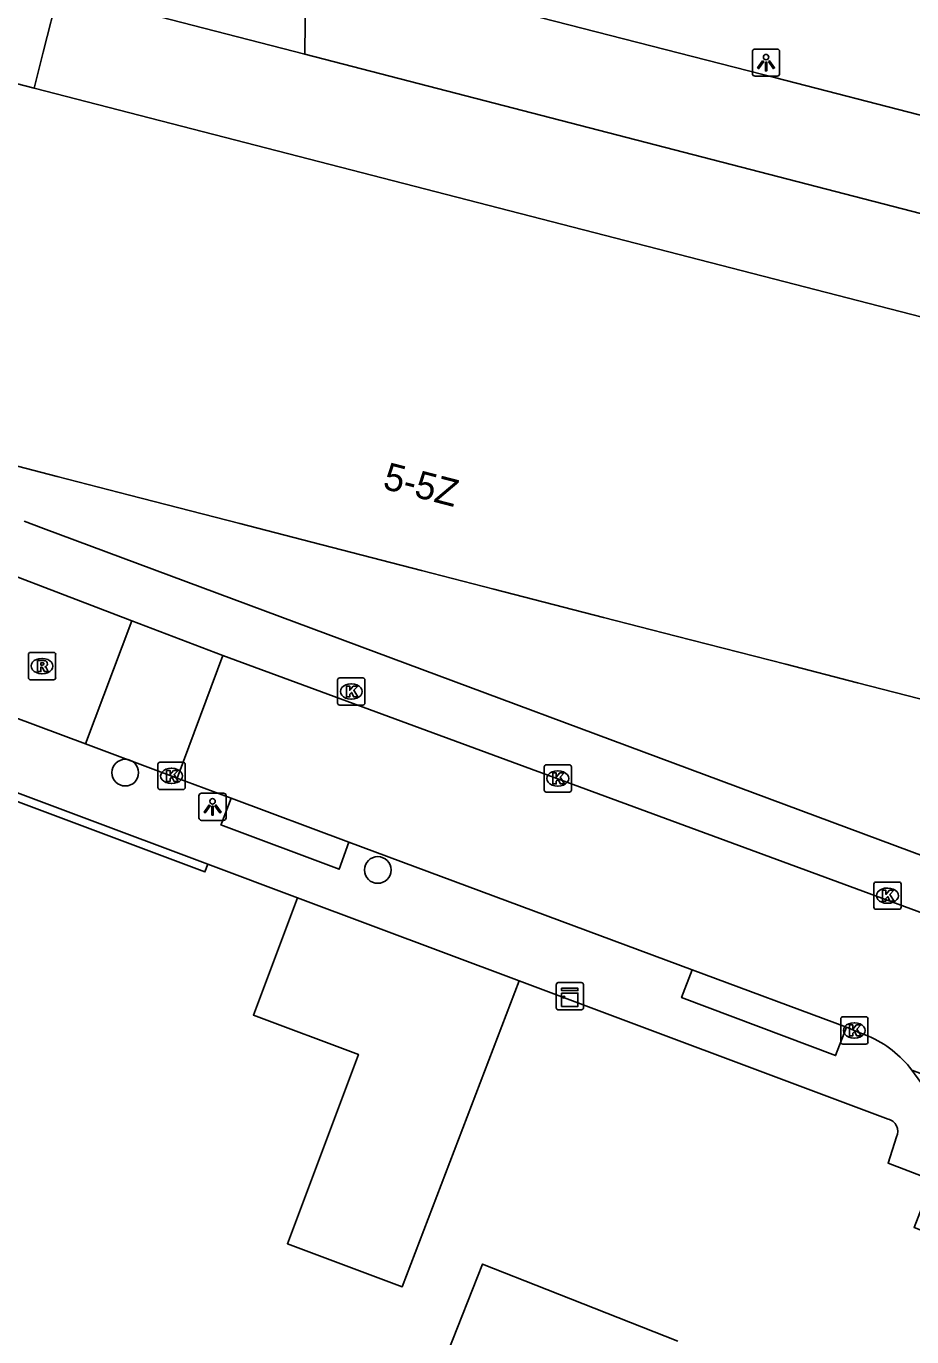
# Model space of a CAD drawing. Extents: x 160664 to 161506, y 382245 to 383288.
# Drawn here: x 161194.13 to 161226.63, y 382834.13 to 382882.22 of the extents above; entities that cross this region are included whole.
import ezdxf

# ---------------------------------------------------------------- set-up
doc = ezdxf.new("R2010")
doc.units = 0
for name, color, linetype in [('IMGEO_Boom', 7, 'Continuous'), ('IMGEO_Kast', 7, 'Continuous'), ('IMGEO_Kolk', 7, 'Continuous'), ('IMGEO_Lichtpunt', 7, 'Continuous'), ('IMGEO_Muur', 7, 'Continuous'), ('IMGEO_Pand', 7, 'Continuous'), ('IMGEO_Pand_nummerreeks', 7, 'Continuous'), ('IMGEO_Rijbaan_lokaal_open', 7, 'Continuous'), ('IMGEO_Rioolput', 7, 'Continuous'), ('IMGEO_Voetpad_open', 7, 'Continuous')]:
    doc.layers.add(name, color=color, linetype=linetype)

msp = doc.modelspace()

# ---------------------------------------------------------------- linework, layer by layer
at = {"layer": 'IMGEO_Boom'}
for centre in [(161197.768, 382854.83), (161207.033, 382851.258)]:
    msp.add_circle(centre, 0.489, dxfattribs=at)
at = {"layer": 'IMGEO_Kast'}
for p, q in [((161213.582, 382846.202), (161213.582, 382847.043)), ((161213.582, 382847.043), (161213.582, 382846.202)), ((161213.657, 382847.127), (161214.498, 382847.127)), ((161214.498, 382847.127), (161213.657, 382847.127)), ((161214.582, 382847.052), (161214.582, 382846.211)), ((161214.582, 382846.211), (161214.582, 382847.052)), ((161214.507, 382846.127), (161213.666, 382846.127)), ((161213.666, 382846.127), (161214.507, 382846.127))]:
    msp.add_line(p, q, dxfattribs=at)
for points in [[(161213.777, 382846.917), (161214.377, 382846.917), (161214.377, 382846.832), (161213.777, 382846.832), (161213.777, 382846.917)], [(161213.777, 382846.742), (161214.377, 382846.742), (161214.377, 382846.253), (161213.777, 382846.253), (161213.777, 382846.742)]]:
    msp.add_lwpolyline(points, dxfattribs=at)
msp.add_circle((161213.861, 382846.591), 0.0377, dxfattribs=at)
for centre, start, end in [((161213.66, 382847.049), 92.4484, 184.2845), ((161213.66, 382847.049), 92.4484, 184.2845), ((161214.504, 382847.049), 2.4484, 94.2845), ((161214.504, 382847.049), 2.4484, 94.2845), ((161213.66, 382846.205), 182.4484, 274.2845), ((161213.66, 382846.205), 182.4484, 274.2845), ((161214.504, 382846.205), 272.4484, 4.2845), ((161214.504, 382846.205), 272.4484, 4.2845)]:
    msp.add_arc(centre, 0.0779, start, end, dxfattribs=at)
at = {"layer": 'IMGEO_Kolk'}
for p, q in [((161205.561, 382857.382), (161205.561, 382858.234)), ((161205.636, 382858.308), (161206.488, 382858.308)), ((161206.049, 382858.088), (161206.074, 382858.088)), ((161206.562, 382858.234), (161206.562, 382857.382)), ((161206.072, 382857.528), (161206.047, 382857.528)), ((161206.488, 382857.308), (161205.636, 382857.308)), ((161198.966, 382854.284), (161198.966, 382855.136)), ((161199.041, 382855.21), (161199.893, 382855.21)), ((161199.967, 382855.136), (161199.967, 382854.284)), ((161213.215, 382855.118), (161214.067, 382855.118)), ((161199.454, 382854.99), (161199.479, 382854.99)), ((161213.14, 382854.192), (161213.14, 382855.044)), ((161213.628, 382854.898), (161213.653, 382854.898)), ((161214.141, 382855.044), (161214.141, 382854.192)), ((161199.893, 382854.21), (161199.041, 382854.21)), ((161199.477, 382854.43), (161199.452, 382854.43)), ((161214.067, 382854.118), (161213.215, 382854.118)), ((161213.651, 382854.338), (161213.626, 382854.338)), ((161225.236, 382849.889), (161225.236, 382850.741)), ((161225.311, 382850.815), (161226.163, 382850.815)), ((161226.237, 382850.741), (161226.237, 382849.889)), ((161225.724, 382850.595), (161225.749, 382850.595)), ((161226.163, 382849.815), (161225.311, 382849.815)), ((161225.747, 382850.035), (161225.722, 382850.035)), ((161224.021, 382844.944), (161224.021, 382845.796)), ((161224.096, 382845.87), (161224.948, 382845.87)), ((161224.509, 382845.65), (161224.534, 382845.65)), ((161225.022, 382845.796), (161225.022, 382844.944)), ((161224.532, 382845.09), (161224.507, 382845.09)), ((161224.948, 382844.87), (161224.096, 382844.87))]:
    msp.add_line(p, q, dxfattribs=at)
for points in [[(161205.561, 382857.382), (161205.561, 382858.234)], [(161205.636, 382858.308), (161206.488, 382858.308)], [(161205.882, 382858.008), (161206.005, 382858.008), (161206.005, 382857.857), (161206.135, 382858.008), (161206.299, 382858.008), (161206.153, 382857.857), (161206.306, 382857.608), (161206.154, 382857.608), (161206.069, 382857.772), (161206.005, 382857.705), (161206.005, 382857.608), (161205.882, 382857.608), (161205.882, 382858.008)], [(161206.562, 382858.234), (161206.562, 382857.382)], [(161206.488, 382857.308), (161205.636, 382857.308)], [(161198.966, 382854.284), (161198.966, 382855.136)], [(161199.041, 382855.21), (161199.893, 382855.21)], [(161199.967, 382855.136), (161199.967, 382854.284)], [(161213.215, 382855.118), (161214.067, 382855.118)], [(161199.287, 382854.91), (161199.41, 382854.91), (161199.41, 382854.759), (161199.54, 382854.91), (161199.704, 382854.91), (161199.558, 382854.759), (161199.711, 382854.51), (161199.559, 382854.51), (161199.474, 382854.674), (161199.41, 382854.607), (161199.41, 382854.51), (161199.287, 382854.51), (161199.287, 382854.91)], [(161213.14, 382854.192), (161213.14, 382855.044)], [(161213.461, 382854.818), (161213.584, 382854.818), (161213.584, 382854.667), (161213.714, 382854.818), (161213.878, 382854.818), (161213.732, 382854.667), (161213.885, 382854.418), (161213.733, 382854.418), (161213.648, 382854.582), (161213.584, 382854.515), (161213.584, 382854.418), (161213.461, 382854.418), (161213.461, 382854.818)], [(161214.141, 382855.044), (161214.141, 382854.192)], [(161199.893, 382854.21), (161199.041, 382854.21)], [(161214.067, 382854.118), (161213.215, 382854.118)], [(161225.236, 382849.889), (161225.236, 382850.741)], [(161225.311, 382850.815), (161226.163, 382850.815)], [(161226.237, 382850.741), (161226.237, 382849.889)], [(161225.557, 382850.515), (161225.68, 382850.515), (161225.68, 382850.364), (161225.81, 382850.515), (161225.974, 382850.515), (161225.828, 382850.364), (161225.981, 382850.115), (161225.829, 382850.115), (161225.744, 382850.279), (161225.68, 382850.212), (161225.68, 382850.115), (161225.557, 382850.115), (161225.557, 382850.515)], [(161226.163, 382849.815), (161225.311, 382849.815)], [(161224.021, 382844.944), (161224.021, 382845.796)], [(161224.096, 382845.87), (161224.948, 382845.87)], [(161224.342, 382845.57), (161224.465, 382845.57), (161224.465, 382845.419), (161224.595, 382845.57), (161224.759, 382845.57), (161224.613, 382845.419), (161224.766, 382845.17), (161224.614, 382845.17), (161224.529, 382845.334), (161224.465, 382845.267), (161224.465, 382845.17), (161224.342, 382845.17), (161224.342, 382845.57)], [(161225.022, 382845.796), (161225.022, 382844.944)], [(161224.948, 382844.87), (161224.096, 382844.87)]]:
    msp.add_lwpolyline(points, dxfattribs=at)
for centre, start, end in [((161205.638, 382858.232), 91.552, 178.448), ((161205.638, 382858.232), 91.552, 178.448), ((161206.486, 382858.232), 1.552, 88.448), ((161206.486, 382858.232), 1.552, 88.448), ((161205.638, 382857.384), 181.552, 268.448), ((161205.638, 382857.384), 181.552, 268.448), ((161206.486, 382857.384), 271.552, 358.448), ((161206.486, 382857.384), 271.552, 358.448), ((161199.043, 382855.134), 91.552, 178.448), ((161199.043, 382855.134), 91.552, 178.448), ((161199.891, 382855.134), 1.552, 88.448), ((161199.891, 382855.134), 1.552, 88.448), ((161213.217, 382855.042), 91.552, 178.448), ((161213.217, 382855.042), 91.552, 178.448), ((161214.065, 382855.042), 1.552, 88.448), ((161214.065, 382855.042), 1.552, 88.448), ((161199.043, 382854.286), 181.552, 268.448), ((161199.043, 382854.286), 181.552, 268.448), ((161199.891, 382854.286), 271.552, 358.448), ((161199.891, 382854.286), 271.552, 358.448), ((161213.217, 382854.194), 181.552, 268.448), ((161213.217, 382854.194), 181.552, 268.448), ((161214.065, 382854.194), 271.552, 358.448), ((161214.065, 382854.194), 271.552, 358.448), ((161225.313, 382850.739), 91.552, 178.448), ((161225.313, 382850.739), 91.552, 178.448), ((161226.161, 382850.739), 1.552, 88.448), ((161226.161, 382850.739), 1.552, 88.448), ((161225.313, 382849.891), 181.552, 268.448), ((161225.313, 382849.891), 181.552, 268.448), ((161226.161, 382849.891), 271.552, 358.448), ((161226.161, 382849.891), 271.552, 358.448), ((161224.098, 382845.794), 91.552, 178.448), ((161224.098, 382845.794), 91.552, 178.448), ((161224.946, 382845.794), 1.552, 88.448), ((161224.946, 382845.794), 1.552, 88.448), ((161224.098, 382844.946), 181.552, 268.448), ((161224.098, 382844.946), 181.552, 268.448), ((161224.946, 382844.946), 271.552, 358.448), ((161224.946, 382844.946), 271.552, 358.448)]:
    msp.add_arc(centre, 0.0765, start, end, dxfattribs=at)
for centre, major_axis, ratio, start_param, end_param in [((161206.048, 382857.808), (-0.387, 0.002), 0.722429, 4.712389, 7.853982), ((161206.073, 382857.808), (-0.39, 0.002), 0.717154, 1.570796, 4.712389), ((161199.453, 382854.71), (-0.387, 0.002), 0.722429, 4.712389, 7.853982), ((161199.478, 382854.71), (-0.39, 0.002), 0.717154, 1.570796, 4.712389), ((161213.627, 382854.618), (-0.387, 0.002), 0.722429, 4.712389, 7.853982), ((161213.652, 382854.618), (-0.39, 0.002), 0.717154, 1.570796, 4.712389), ((161225.723, 382850.315), (-0.387, 0.002), 0.722429, 4.712389, 7.853982), ((161225.748, 382850.315), (-0.39, 0.002), 0.717154, 1.570796, 4.712389), ((161224.508, 382845.37), (-0.387, 0.002), 0.722429, 4.712389, 7.853982), ((161224.533, 382845.37), (-0.39, 0.002), 0.717154, 1.570796, 4.712389)]:
    msp.add_ellipse(centre, major_axis=major_axis, ratio=ratio, start_param=start_param, end_param=end_param, dxfattribs=at)
at = {"layer": 'IMGEO_Lichtpunt'}
for p, q in [((161220.783, 382881.29), (161220.783, 382880.483)), ((161220.783, 382881.29), (161220.783, 382880.483)), ((161221.685, 382881.385), (161220.877, 382881.385)), ((161221.685, 382881.385), (161220.877, 382881.385)), ((161221.779, 382880.483), (161221.779, 382881.29)), ((161221.779, 382880.483), (161221.779, 382881.29)), ((161220.877, 382880.389), (161221.685, 382880.389)), ((161220.877, 382880.389), (161221.685, 382880.389)), ((161200.471, 382853.981), (161200.471, 382853.174)), ((161200.471, 382853.981), (161200.471, 382853.174)), ((161201.373, 382854.076), (161200.565, 382854.076)), ((161201.373, 382854.076), (161200.565, 382854.076)), ((161201.467, 382853.174), (161201.467, 382853.981)), ((161201.467, 382853.174), (161201.467, 382853.981)), ((161200.565, 382853.08), (161201.373, 382853.08)), ((161200.565, 382853.08), (161201.373, 382853.08))]:
    msp.add_line(p, q, dxfattribs=at)
for points in [[(161221.157, 382880.954), (161221.196, 382880.926), (161221.008, 382880.664), (161220.97, 382880.691), (161221.157, 382880.954)], [(161221.259, 382880.906), (161221.306, 382880.906), (161221.306, 382880.584), (161221.259, 382880.584), (161221.259, 382880.906)], [(161221.369, 382880.926), (161221.407, 382880.953), (161221.594, 382880.691), (161221.555, 382880.663), (161221.369, 382880.926)], [(161200.845, 382853.645), (161200.884, 382853.617), (161200.696, 382853.355), (161200.658, 382853.382), (161200.845, 382853.645)], [(161201.057, 382853.617), (161201.095, 382853.644), (161201.282, 382853.382), (161201.243, 382853.354), (161201.057, 382853.617)], [(161200.947, 382853.597), (161200.994, 382853.597), (161200.994, 382853.275), (161200.947, 382853.275), (161200.947, 382853.597)]]:
    msp.add_lwpolyline(points, dxfattribs=at)
for centre in [(161221.282, 382881.088), (161200.97, 382853.779)]:
    msp.add_circle(centre, 0.0994, dxfattribs=at)
for centre, start, end in [((161220.877, 382881.29), 90, 180), ((161220.877, 382881.29), 90, 180), ((161221.685, 382881.29), 0, 90), ((161221.685, 382881.29), 0, 90), ((161220.877, 382880.483), 180, 270), ((161220.877, 382880.483), 180, 270), ((161221.685, 382880.483), 270, 0), ((161221.685, 382880.483), 270, 360), ((161200.565, 382853.981), 90, 180), ((161200.565, 382853.981), 90, 180), ((161201.373, 382853.981), 0, 90), ((161201.373, 382853.981), 0, 90), ((161200.565, 382853.174), 180, 270), ((161200.565, 382853.174), 180, 270), ((161201.373, 382853.174), 270, 0), ((161201.373, 382853.174), 270, 360)]:
    msp.add_arc(centre, 0.0946, start, end, dxfattribs=at)
at = {"layer": 'IMGEO_Muur'}
for points in [[(161200.797, 382851.469), (161200.693, 382851.188), (161186.678, 382856.433), (161186.783, 382856.714)], [(161186.783, 382856.714), (161200.797, 382851.469)]]:
    msp.add_lwpolyline(points, dxfattribs=at)
at = {"layer": 'IMGEO_Pand'}
for points in [[(161188.463, 382879.139), (161189.027, 382881.34), (161194.426, 382879.948)], [(161194.426, 382879.948), (161234.744, 382869.554)], [(161185.655, 382868.227), (161191.219, 382866.746), (161195.266, 382865.7), (161197.929, 382865.011), (161201.968, 382863.97), (161204.612, 382863.289), (161208.643, 382862.248), (161211.294, 382861.564), (161215.316, 382860.529), (161217.986, 382859.841), (161222.003, 382858.807), (161224.643, 382858.128), (161228.68, 382857.091), (161231.511, 382856.364)], [(161212.218, 382847.191), (161207.931, 382835.961), (161203.717, 382837.54), (161206.321, 382844.488), (161202.473, 382845.931), (161204.087, 382850.237)], [(161204.087, 382850.237), (161212.218, 382847.191)], [(161209.036, 382832.145), (161210.872, 382836.795), (161213.235, 382835.862), (161218.046, 382833.963)]]:
    msp.add_lwpolyline(points, dxfattribs=at)
at = {"layer": 'IMGEO_Rijbaan_lokaal_open'}
for points in [[(161204.395, 382884.755), (161204.363, 382881.199)], [(161204.363, 382881.199), (161195.334, 382883.537), (161194.761, 382881.272), (161194.426, 382879.948)], [(161198.012, 382860.405), (161190.717, 382863.193)], [(161196.311, 382855.883), (161198.012, 382860.405)], [(161201.348, 382859.129), (161198.012, 382860.405)], [(161201.348, 382859.129), (161199.674, 382854.633)], [(161237.374, 382845.875), (161230.675, 382848.332), (161201.348, 382859.129)], [(161190.071, 382858.208), (161196.311, 382855.883)], [(161199.674, 382854.633), (161196.311, 382855.883)], [(161199.674, 382854.633), (161201.653, 382853.895)], [(161201.653, 382853.895), (161205.976, 382852.285)], [(161205.976, 382852.285), (161218.565, 382847.595)], [(161218.565, 382847.595), (161224.23, 382845.484)], [(161224.23, 382845.484), (161224.718, 382845.285), (161225.037, 382845.163)], [(161242.657, 382835.403), (161243.513, 382837.578), (161226.629, 382843.915)]]:
    msp.add_lwpolyline(points, dxfattribs=at)
msp.add_arc((161223.439, 382841.485), 4.011, 37.2994, 66.5134, dxfattribs=at)
at = {"layer": 'IMGEO_Rioolput'}
for p, q in [((161194.213, 382858.316), (161194.213, 382859.168)), ((161194.288, 382859.242), (161195.14, 382859.242)), ((161194.701, 382859.022), (161194.726, 382859.022)), ((161195.214, 382859.168), (161195.214, 382858.316)), ((161194.724, 382858.462), (161194.699, 382858.462)), ((161195.14, 382858.242), (161194.288, 382858.242))]:
    msp.add_line(p, q, dxfattribs=at)
for points in [[(161194.213, 382858.316), (161194.213, 382859.168)], [(161194.288, 382859.242), (161195.14, 382859.242)], [(161194.802, 382858.94), (161194.55, 382858.942), (161194.55, 382858.542)], [(161195.214, 382859.168), (161195.214, 382858.316)], [(161194.55, 382858.542), (161194.674, 382858.542), (161194.674, 382858.704), (161194.685, 382858.704)], [(161194.728, 382858.861), (161194.674, 382858.861), (161194.674, 382858.78)], [(161194.674, 382858.78), (161194.726, 382858.78)], [(161194.732, 382858.675), (161194.803, 382858.542), (161194.943, 382858.542), (161194.878, 382858.668)], [(161195.14, 382858.242), (161194.288, 382858.242)]]:
    msp.add_lwpolyline(points, dxfattribs=at)
for centre, radius, start, end in [((161194.29, 382859.166), 0.0765, 91.552, 178.448), ((161194.29, 382859.166), 0.0765, 91.552, 178.448), ((161194.801, 382858.83), 0.109, 350.3612, 89.416), ((161195.138, 382859.166), 0.0765, 1.552, 88.448), ((161195.138, 382859.166), 0.0765, 1.552, 88.448), ((161194.684, 382858.651), 0.0533, 26.0293, 88.6989), ((161194.71, 382858.969), 0.19, 274.7715, 282.9687), ((161194.734, 382858.765), 0.0964, 77.0061, 93.1865), ((161194.748, 382858.822), 0.0378, 276.6634, 79.6772), ((161194.799, 382858.83), 0.112, 277.5842, 350.9817), ((161194.783, 382858.615), 0.108, 29.5134, 73.7905), ((161194.29, 382858.318), 0.0765, 181.552, 268.448), ((161194.29, 382858.318), 0.0765, 181.552, 268.448), ((161195.138, 382858.318), 0.0765, 271.552, 358.448), ((161195.138, 382858.318), 0.0765, 271.552, 358.448)]:
    msp.add_arc(centre, radius, start, end, dxfattribs=at)
for centre, major_axis, ratio, start_param, end_param in [((161194.7, 382858.742), (-0.387, 0.002), 0.722429, 4.712389, 7.853982), ((161194.725, 382858.742), (-0.39, 0.002), 0.717154, 1.570796, 4.712389)]:
    msp.add_ellipse(centre, major_axis=major_axis, ratio=ratio, start_param=start_param, end_param=end_param, dxfattribs=at)
at = {"layer": 'IMGEO_Voetpad_open'}
for points in [[(161204.395, 382884.755), (161221.635, 382880.325), (161238.405, 382875.998), (161237.571, 382898.417), (161237.023, 382912.84), (161230.627, 382912.589), (161227.102, 382927.696), (161203.004, 382921.558)], [(161234.744, 382869.554), (161235.097, 382870.943), (161235.646, 382873.1), (161204.363, 382881.199)], [(161194.053, 382864.055), (161194.771, 382863.788), (161231.233, 382850.215), (161234.998, 382848.832)], [(161205.976, 382852.285), (161205.612, 382851.287), (161201.277, 382852.912), (161201.295, 382852.959), (161201.653, 382853.895)], [(161204.087, 382850.237), (161200.797, 382851.469)], [(161224.23, 382845.484), (161223.832, 382844.445), (161218.183, 382846.578), (161218.565, 382847.595)], [(161225.768, 382842.117), (161212.218, 382847.191)], [(161226.629, 382843.915), (161228.741, 382841.015)], [(161247.543, 382790.576), (161243.275, 382831.841), (161235.463, 382834.768), (161235.153, 382834.791), (161226.716, 382838.135), (161227.393, 382839.873), (161225.76, 382840.503), (161226.068, 382841.467)]]:
    msp.add_lwpolyline(points, dxfattribs=at)
msp.add_arc((161225.655, 382841.671), 0.46, 333.7296, 75.8207, dxfattribs=at)

# ---------------------------------------------------------------- texts
at = {"layer": 'IMGEO_Pand_nummerreeks'}
msp.add_text('5-5Z', height=1, rotation=345.4955, dxfattribs=at).set_placement((161207.178, 382865.262))

doc.saveas('drawing.dxf')
